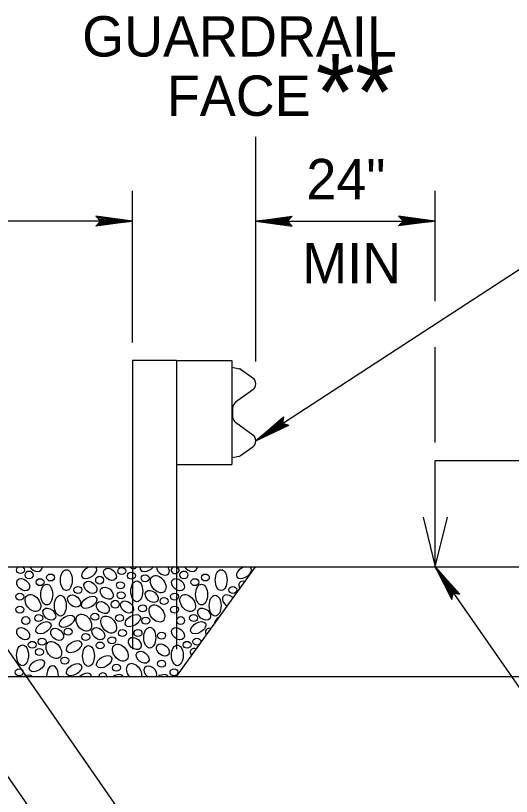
# Model space of a CAD drawing. Extents: x 1252282 to 1252638, y 733735 to 733845.
# Drawn here: x 1252562.97 to 1252571.3, y 733777.72 to 733790.84 of the extents above; entities that cross this region are included whole.
import ezdxf

# ---------------------------------------------------------------- set-up
doc = ezdxf.new("R2010")
doc.units = 0
doc.layers.add('Default', color=7, linetype='Continuous')

msp = doc.modelspace()

# ---------------------------------------------------------------- linework, layer by layer
at = {"layer": 'Default'}
for p, q in [((1252567.007, 733785.029), (1252567.007, 733788.802)), ((1252567.007, 733783.693), (1252574.448, 733788.537)), ((1252564.932, 733785.35), (1252564.932, 733787.894)), ((1252570.021, 733786.043), (1252570.021, 733787.894)), ((1252564.932, 733787.388), (1252564.32, 733787.471)), ((1252564.399, 733787.388), (1252564.32, 733787.471)), ((1252567.007, 733787.388), (1252567.619, 733787.471)), ((1252567.54, 733787.388), (1252567.619, 733787.471)), ((1252570.021, 733787.388), (1252569.408, 733787.472)), ((1252569.408, 733787.472), (1252569.487, 733787.388)), ((1252564.932, 733787.388), (1252549.735, 733787.388)), ((1252564.932, 733787.388), (1252564.32, 733787.305)), ((1252564.32, 733787.305), (1252564.399, 733787.388)), ((1252564.932, 733787.388), (1252564.331, 733787.459)), ((1252564.331, 733787.317), (1252564.932, 733787.388)), ((1252564.343, 733787.448), (1252564.932, 733787.388)), ((1252564.932, 733787.388), (1252564.343, 733787.329)), ((1252564.932, 733787.388), (1252564.354, 733787.436)), ((1252564.354, 733787.341), (1252564.932, 733787.388)), ((1252564.365, 733787.423), (1252564.932, 733787.388)), ((1252564.932, 733787.388), (1252564.365, 733787.353)), ((1252564.932, 733787.388), (1252564.376, 733787.412)), ((1252564.376, 733787.364), (1252564.932, 733787.388)), ((1252564.388, 733787.4), (1252564.932, 733787.388)), ((1252564.932, 733787.388), (1252564.388, 733787.376)), ((1252564.399, 733787.388), (1252564.932, 733787.388)), ((1252567.007, 733787.388), (1252567.608, 733787.459)), ((1252567.596, 733787.448), (1252567.007, 733787.388)), ((1252567.007, 733787.388), (1252567.585, 733787.436)), ((1252567.573, 733787.423), (1252567.007, 733787.388)), ((1252567.007, 733787.388), (1252567.563, 733787.412)), ((1252567.551, 733787.4), (1252567.007, 733787.388)), ((1252567.007, 733787.388), (1252567.619, 733787.305)), ((1252567.608, 733787.317), (1252567.007, 733787.388)), ((1252567.007, 733787.388), (1252567.596, 733787.329)), ((1252567.585, 733787.341), (1252567.007, 733787.388)), ((1252567.007, 733787.388), (1252567.573, 733787.353)), ((1252567.563, 733787.364), (1252567.007, 733787.388)), ((1252567.007, 733787.388), (1252567.551, 733787.376)), ((1252567.54, 733787.388), (1252567.007, 733787.388)), ((1252567.007, 733787.388), (1252570.021, 733787.388)), ((1252567.619, 733787.305), (1252567.54, 733787.388)), ((1252570.021, 733787.388), (1252569.408, 733787.306)), ((1252569.487, 733787.388), (1252569.408, 733787.306)), ((1252569.42, 733787.46), (1252570.021, 733787.388)), ((1252570.021, 733787.388), (1252569.42, 733787.318)), ((1252570.021, 733787.388), (1252569.431, 733787.448)), ((1252569.431, 733787.329), (1252570.021, 733787.388)), ((1252569.442, 733787.436), (1252570.021, 733787.388)), ((1252570.021, 733787.388), (1252569.442, 733787.341)), ((1252570.021, 733787.388), (1252569.454, 733787.424)), ((1252569.454, 733787.354), (1252570.021, 733787.388)), ((1252569.465, 733787.413), (1252570.021, 733787.388)), ((1252570.021, 733787.388), (1252569.465, 733787.365)), ((1252570.021, 733787.388), (1252569.476, 733787.401)), ((1252569.476, 733787.377), (1252570.021, 733787.388)), ((1252569.487, 733787.388), (1252570.021, 733787.388)), ((1252570.021, 733783.668), (1252570.021, 733785.268)), ((1252564.932, 733785.047), (1252564.932, 733780.195)), ((1252565.675, 733785.047), (1252564.932, 733785.047)), ((1252565.675, 733785.047), (1252566.604, 733785.047)), ((1252565.675, 733785.047), (1252565.675, 733780.195)), ((1252566.604, 733785.047), (1252566.604, 733783.298)), ((1252566.604, 733784.931), (1252566.734, 733784.907)), ((1252566.752, 733784.899), (1252566.957, 733784.751)), ((1252566.957, 733784.554), (1252566.667, 733784.343)), ((1252566.618, 733784.244), (1252566.618, 733784.101)), ((1252567.007, 733783.693), (1252567.475, 733784.097)), ((1252567.472, 733784.081), (1252567.007, 733783.693)), ((1252567.007, 733783.693), (1252567.468, 733784.065)), ((1252567.475, 733784.097), (1252567.454, 733783.984)), ((1252566.957, 733783.792), (1252566.667, 733784.002)), ((1252567.466, 733784.049), (1252567.007, 733783.693)), ((1252567.007, 733783.693), (1252567.462, 733784.032)), ((1252567.46, 733784.017), (1252567.007, 733783.693)), ((1252567.007, 733783.693), (1252567.456, 733784)), ((1252567.454, 733783.984), (1252567.007, 733783.693)), ((1252567.469, 733783.981), (1252567.007, 733783.693)), ((1252567.007, 733783.693), (1252567.486, 733783.977)), ((1252567.501, 733783.973), (1252567.007, 733783.693)), ((1252567.007, 733783.693), (1252567.517, 733783.969)), ((1252567.533, 733783.965), (1252567.007, 733783.693)), ((1252567.007, 733783.693), (1252567.549, 733783.962)), ((1252567.007, 733783.693), (1252567.565, 733783.958)), ((1252567.454, 733783.984), (1252567.565, 733783.958)), ((1252558.904, 733783.702), (1252565.882, 733773.673)), ((1252566.752, 733783.447), (1252566.957, 733783.595)), ((1252566.604, 733783.414), (1252566.734, 733783.438)), ((1252565.675, 733783.298), (1252566.604, 733783.298)), ((1252570.021, 733781.576), (1252570.021, 733783.365)), ((1252570.021, 733783.365), (1252584.331, 733783.365)), ((1252558.904, 733781.576), (1252564.932, 733781.576)), ((1252564.932, 733781.576), (1252565.675, 733781.576)), ((1252565.675, 733779.735), (1252567.004, 733781.576)), ((1252565.675, 733781.576), (1252587.491, 733781.576)), ((1252570.021, 733781.576), (1252570.438, 733781.12)), ((1252570.021, 733781.576), (1252570.302, 733781.026)), ((1252570.305, 733781.042), (1252570.021, 733781.576)), ((1252570.021, 733781.576), (1252570.308, 733781.058)), ((1252570.312, 733781.074), (1252570.021, 733781.576)), ((1252570.021, 733781.576), (1252570.315, 733781.091)), ((1252570.318, 733781.106), (1252570.021, 733781.576)), ((1252570.021, 733781.576), (1252570.321, 733781.122)), ((1252570.325, 733781.138), (1252570.021, 733781.576)), ((1252570.341, 733781.136), (1252570.021, 733781.576)), ((1252570.021, 733781.576), (1252570.357, 733781.133)), ((1252570.373, 733781.131), (1252570.021, 733781.576)), ((1252570.021, 733781.576), (1252570.39, 733781.128)), ((1252570.406, 733781.126), (1252570.021, 733781.576)), ((1252570.021, 733781.576), (1252570.422, 733781.123)), ((1252570.021, 733781.576), (1252572.562, 733777.925)), ((1252570.302, 733781.026), (1252570.325, 733781.138)), ((1252570.325, 733781.138), (1252570.438, 733781.12)), ((1252562.503, 733780.655), (1252565.882, 733775.799)), ((1252558.904, 733779.735), (1252565.675, 733779.735)), ((1252565.675, 733779.735), (1252587.491, 733779.735))]:
    msp.add_line(p, q, dxfattribs=at)
msp.add_lwpolyline([(1252569.819, 733782.412), (1252570.021, 733781.576), (1252570.232, 733782.412)], dxfattribs=at)
for centre in [(1252563.197, 733781.44), (1252565.799, 733781.44), (1252564.382, 733781.353), (1252564.645, 733780.948), (1252563.142, 733780.673), (1252565.744, 733780.673)]:
    msp.add_circle(centre, 0.0664, dxfattribs=at)
msp.add_arc((1252564.436, 733779.729), 0.0664, 5.2245, 174.7755, dxfattribs=at)
for centre, major_axis, ratio, start_param, end_param in [((1252566.724, 733784.86), (0.0019, 0.0481), 0.965519, 5.680593, 6.113127), ((1252566.891, 733784.652), (0, 0.12), 0.965519, 3.752668, 5.67197), ((1252566.734, 733784.245), (0, 0.12), 0.965519, 0.611926, 1.570796), ((1252566.734, 733784.101), (0, -0.12), 0.965519, 4.712389, 5.671259), ((1252566.891, 733783.693), (0, 0.12), 0.965519, 3.752808, 5.67211), ((1252566.724, 733783.485), (0.0019, -0.0481), 0.965519, 0.170059, 0.602592), ((1252563.292, 733781.643), (-0.098, 0.128), 0.683378, 1.56885, 3.747854), ((1252564.206, 733781.484), (-0.12, -0.076), 0.580318, 4.348334, 9.69677), ((1252564.949, 733781.604), (0.067, 0), 0.86851, 3.638307, 5.78647), ((1252565.192, 733781.604), (-0.12, -0.076), 0.580318, 5.723453, 8.32165), ((1252565.445, 733781.539), (-0.0946, 0.0788), 0.692349, 0.500409, 4.396271), ((1252565.652, 733781.522), (0.067, 0), 0.86851, 1.938225, 7.486553), ((1252565.894, 733781.643), (-0.098, 0.128), 0.683378, 1.56885, 3.747854), ((1252566.808, 733781.484), (-0.12, -0.076), 0.580318, 4.348334, 9.69677), ((1252566.829, 733781.231), (-0.0946, 0.0788), 0.692349, 5.271932, 7.39096), ((1252566.555, 733781.002), (-0.0946, 0.0788), 0.692349, 4.528936, 8.133956), ((1252566.435, 733780.662), (-0.12, -0.076), 0.580318, 4.65028, 5.977333), ((1252566.27, 733780.443), (-0.0946, 0.0788), 0.692349, 5.345939, 7.316953), ((1252565.972, 733780.145), (0.067, 0), 0.86851, 1.021949, 4.141541), ((1252563.591, 733779.739), (0, -0.175), 0.570345, 1.542964, 4.740222), ((1252564.962, 733779.805), (-0.098, 0.128), 0.683378, 3.719822, 7.880068), ((1252565.236, 733779.805), (-0.0946, 0.0788), 0.692349, 3.262394, 7.917471), ((1252563.13, 733779.652), (-0.12, -0.076), 0.580318, 3.233074, 4.528845), ((1252564.118, 733779.685), (-0.12, -0.076), 0.580318, 2.811607, 4.950312), ((1252564.655, 733779.663), (-0.12, -0.076), 0.580318, 3.074149, 4.687769), ((1252565.412, 733779.663), (-0.12, -0.076), 0.580318, 3.074149, 4.687769)]:
    msp.add_ellipse(centre, major_axis=major_axis, ratio=ratio, start_param=start_param, end_param=end_param, dxfattribs=at)
for centre, major_axis, ratio in [((1252563.05, 733781.522), (0.067, 0), 0.86851), ((1252564.556, 733781.451), (-0.0946, 0.0788), 0.692349), ((1252563.557, 733781.397), (0.067, 0), 0.86851), ((1252563.823, 733781.354), (0, -0.175), 0.570345), ((1252564.753, 733781.506), (0.067, 0), 0.86851), ((1252564.916, 733781.428), (0.067, 0), 0.86851), ((1252565.147, 733781.384), (0.067, 0), 0.86851), ((1252565.367, 733781.286), (-0.098, 0.128), 0.683378), ((1252566.159, 733781.397), (0.067, 0), 0.86851), ((1252566.425, 733781.354), (0, -0.175), 0.570345), ((1252563.097, 733781.277), (-0.0946, 0.0788), 0.692349), ((1252563.381, 733781.319), (0.067, 0), 0.86851), ((1252564.227, 733781.231), (-0.0946, 0.0788), 0.692349), ((1252564.731, 733781.266), (0.067, 0), 0.86851), ((1252565.007, 733781.166), (0, -0.175), 0.570345), ((1252565.699, 733781.277), (-0.0946, 0.0788), 0.692349), ((1252565.983, 733781.319), (0.067, 0), 0.86851), ((1252563.493, 733781.111), (0, -0.175), 0.570345), ((1252564.018, 733781.188), (0.067, 0), 0.86851), ((1252564.502, 733781.133), (-0.0946, 0.0788), 0.692349), ((1252565.258, 733781.079), (-0.0946, 0.0788), 0.692349), ((1252566.095, 733781.111), (0, -0.175), 0.570345), ((1252566.621, 733781.188), (0.067, 0), 0.86851), ((1252563.041, 733781.077), (0.067, 0), 0.86851), ((1252563.261, 733780.968), (-0.098, 0.128), 0.683378), ((1252563.722, 733780.924), (0, -0.175), 0.570345), ((1252563.953, 733781.002), (-0.0946, 0.0788), 0.692349), ((1252564.206, 733780.979), (-0.12, -0.076), 0.580318), ((1252564.742, 733781.099), (0.067, 0), 0.86851), ((1252565.465, 733781.001), (0.067, 0), 0.86851), ((1252565.643, 733781.077), (0.067, 0), 0.86851), ((1252565.863, 733780.968), (-0.098, 0.128), 0.683378), ((1252566.324, 733780.924), (0, -0.175), 0.570345), ((1252563.041, 733780.857), (0.067, 0), 0.86851), ((1252564.436, 733780.892), (-0.0946, 0.0788), 0.692349), ((1252564.842, 733780.902), (-0.0946, 0.0788), 0.692349), ((1252565.104, 733780.879), (0.067, 0), 0.86851), ((1252565.345, 733780.793), (-0.098, 0.128), 0.683378), ((1252565.643, 733780.857), (0.067, 0), 0.86851), ((1252563.537, 733780.782), (-0.0946, 0.0788), 0.692349), ((1252564.117, 733780.639), (-0.098, 0.128), 0.683378), ((1252564.302, 733780.737), (0.067, 0), 0.86851), ((1252564.94, 733780.672), (-0.12, -0.076), 0.580318), ((1252566.139, 733780.782), (-0.0946, 0.0788), 0.692349), ((1252563.359, 733780.715), (0.067, 0), 0.86851), ((1252563.437, 733780.552), (-0.12, -0.076), 0.580318), ((1252563.833, 733780.662), (-0.12, -0.076), 0.580318), ((1252564.535, 733780.606), (-0.098, 0.128), 0.683378), ((1252564.718, 733780.715), (0.067, 0), 0.86851), ((1252565.158, 733780.672), (0.067, 0), 0.86851), ((1252565.961, 733780.715), (0.067, 0), 0.86851), ((1252566.039, 733780.552), (-0.12, -0.076), 0.580318), ((1252563.097, 733780.453), (-0.0946, 0.0788), 0.692349), ((1252563.668, 733780.443), (-0.0946, 0.0788), 0.692349), ((1252563.853, 733780.486), (0.067, 0), 0.86851), ((1252564.36, 733780.453), (-0.0946, 0.0788), 0.692349), ((1252564.764, 733780.463), (0.067, 0), 0.86851), ((1252565.027, 733780.464), (0.067, 0), 0.86851), ((1252565.225, 733780.386), (0, -0.175), 0.570345), ((1252565.699, 733780.453), (-0.0946, 0.0788), 0.692349), ((1252564.149, 733780.397), (0.067, 0), 0.86851), ((1252564.589, 733780.343), (0.067, 0), 0.86851), ((1252564.974, 733780.288), (-0.0946, 0.0788), 0.692349), ((1252565.423, 733780.421), (0.067, 0), 0.86851), ((1252563.086, 733780.09), (0, -0.175), 0.570345), ((1252563.25, 733780.266), (0.067, 0), 0.86851), ((1252563.414, 733780.319), (0.067, 0), 0.86851), ((1252563.612, 733780.178), (-0.098, 0.128), 0.683378), ((1252563.953, 733780.234), (-0.12, -0.076), 0.580318), ((1252564.195, 733780.079), (0, -0.175), 0.570345), ((1252564.391, 733780.255), (0.067, 0), 0.86851), ((1252564.731, 733780.134), (-0.098, 0.128), 0.683378), ((1252565.445, 733780.179), (-0.0946, 0.0788), 0.692349), ((1252565.688, 733780.09), (0, -0.175), 0.570345), ((1252565.852, 733780.266), (0.067, 0), 0.86851), ((1252566.016, 733780.319), (0.067, 0), 0.86851), ((1252563.37, 733780.145), (0.067, 0), 0.86851), ((1252565.105, 733780.057), (-0.0946, 0.0788), 0.692349), ((1252563.328, 733779.916), (-0.12, -0.076), 0.580318), ((1252563.797, 733780.001), (0.067, 0), 0.86851), ((1252564.458, 733779.981), (-0.12, -0.076), 0.580318), ((1252565.423, 733779.948), (0.067, 0), 0.86851), ((1252563.03, 733779.805), (0.067, 0), 0.86851), ((1252563.953, 733779.849), (-0.12, -0.076), 0.580318), ((1252564.664, 733779.881), (0.067, 0), 0.86851), ((1252565.632, 733779.805), (0.067, 0), 0.86851)]:
    msp.add_ellipse(centre, major_axis=major_axis, ratio=ratio, dxfattribs=at)

# ---------------------------------------------------------------- texts
for s, height, p in [('  GUARDRAIL', 0.67788, (1252563.585, 733790.154)), ('**', 1.271, (1252568.015, 733788.923)), ('FACE', 0.6779, (1252565.512, 733789.157)), ('24"', 0.6779, (1252567.857, 733787.755)), ('MIN', 0.6779, (1252567.788, 733786.344))]:
    msp.add_text(s, height=height, dxfattribs=at).set_placement(p)

doc.saveas('drawing.dxf')
